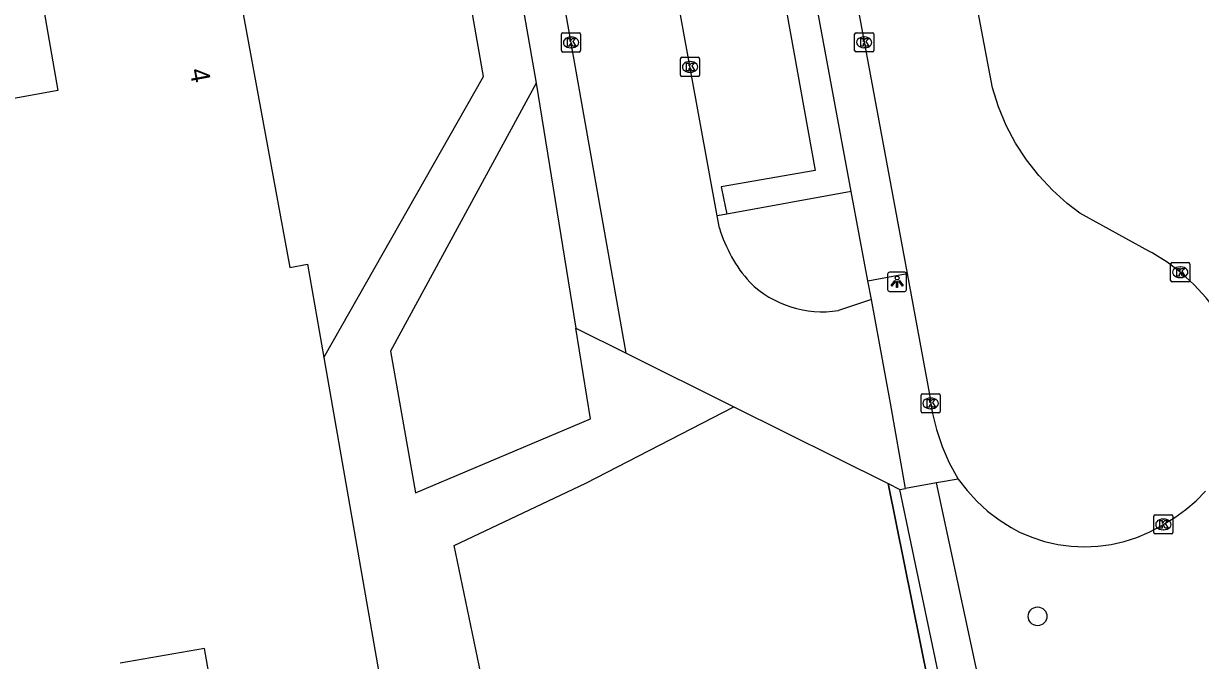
# Model space of a CAD drawing. Extents: x 159451 to 160663, y 388402 to 389723.
# Drawn here: x 159640.5 to 159701.9, y 388842.8 to 388876 of the extents above; entities that cross this region are included whole.
import ezdxf

# ---------------------------------------------------------------- set-up
doc = ezdxf.new("R2010")
doc.units = 0
for name, color, linetype in [('IMGEO_Boom', 7, 'Continuous'), ('IMGEO_Hek', 7, 'Continuous'), ('IMGEO_Kolk', 7, 'Continuous'), ('IMGEO_Lichtpunt', 7, 'Continuous'), ('IMGEO_Loofbos', 7, 'Continuous'), ('IMGEO_Muur', 7, 'Continuous'), ('IMGEO_Pand', 7, 'Continuous'), ('IMGEO_Pand_nummerreeks', 7, 'Continuous'), ('IMGEO_Parkeervlak_open', 7, 'Continuous'), ('IMGEO_Rijbaan_lokaal_open', 7, 'Continuous'), ('IMGEO_Voetpad_halfverhard', 7, 'Continuous'), ('IMGEO_Voetpad_open', 7, 'Continuous')]:
    doc.layers.add(name, color=color, linetype=linetype)

msp = doc.modelspace()

# ---------------------------------------------------------------- linework, layer by layer
at = {"layer": 'IMGEO_Boom'}
msp.add_circle((159693.409, 388845.115), 0.489, dxfattribs=at)
at = {"layer": 'IMGEO_Hek'}
msp.add_lwpolyline([(159685.613, 388852.043), (159688.561, 388837.482)], dxfattribs=at)
at = {"layer": 'IMGEO_Kolk'}
for p, q in [((159668.651, 388875.545), (159669.503, 388875.545)), ((159683.942, 388875.55), (159684.794, 388875.55)), ((159668.576, 388874.619), (159668.576, 388875.471)), ((159669.064, 388875.325), (159669.089, 388875.325)), ((159669.577, 388875.471), (159669.577, 388874.619)), ((159683.867, 388874.624), (159683.867, 388875.476)), ((159684.355, 388875.33), (159684.38, 388875.33)), ((159684.868, 388875.476), (159684.868, 388874.624)), ((159669.503, 388874.545), (159668.651, 388874.545)), ((159669.087, 388874.765), (159669.062, 388874.765)), ((159674.857, 388874.271), (159675.709, 388874.271)), ((159684.794, 388874.55), (159683.942, 388874.55)), ((159684.378, 388874.77), (159684.353, 388874.77)), ((159674.782, 388873.345), (159674.782, 388874.197)), ((159675.27, 388874.051), (159675.295, 388874.051)), ((159675.783, 388874.197), (159675.783, 388873.345)), ((159675.709, 388873.271), (159674.857, 388873.271)), ((159675.293, 388873.491), (159675.268, 388873.491)), ((159700.349, 388862.636), (159700.349, 388863.488)), ((159700.424, 388863.562), (159701.276, 388863.562)), ((159700.837, 388863.342), (159700.862, 388863.342)), ((159701.35, 388863.488), (159701.35, 388862.636)), ((159700.86, 388862.782), (159700.835, 388862.782)), ((159701.276, 388862.562), (159700.424, 388862.562)), ((159687.332, 388855.796), (159687.332, 388856.648)), ((159687.407, 388856.722), (159688.259, 388856.722)), ((159687.82, 388856.502), (159687.845, 388856.502)), ((159688.333, 388856.648), (159688.333, 388855.796)), ((159687.843, 388855.942), (159687.818, 388855.942)), ((159688.259, 388855.722), (159687.407, 388855.722)), ((159699.469, 388849.484), (159699.469, 388850.336)), ((159699.544, 388850.41), (159700.396, 388850.41)), ((159700.47, 388850.336), (159700.47, 388849.484)), ((159699.957, 388850.19), (159699.982, 388850.19)), ((159700.396, 388849.41), (159699.544, 388849.41)), ((159699.98, 388849.63), (159699.955, 388849.63))]:
    msp.add_line(p, q, dxfattribs=at)
for points in [[(159668.651, 388875.545), (159669.503, 388875.545)], [(159683.942, 388875.55), (159684.794, 388875.55)], [(159668.576, 388874.619), (159668.576, 388875.471)], [(159668.897, 388875.245), (159669.02, 388875.245), (159669.02, 388875.094), (159669.15, 388875.245), (159669.314, 388875.245), (159669.168, 388875.094), (159669.321, 388874.845), (159669.169, 388874.845), (159669.084, 388875.009), (159669.02, 388874.942), (159669.02, 388874.845), (159668.897, 388874.845), (159668.897, 388875.245)], [(159669.577, 388875.471), (159669.577, 388874.619)], [(159683.867, 388874.624), (159683.867, 388875.476)], [(159684.188, 388875.25), (159684.311, 388875.25), (159684.311, 388875.099), (159684.441, 388875.25), (159684.605, 388875.25), (159684.459, 388875.099), (159684.612, 388874.85), (159684.46, 388874.85), (159684.375, 388875.014), (159684.311, 388874.947), (159684.311, 388874.85), (159684.188, 388874.85), (159684.188, 388875.25)], [(159684.868, 388875.476), (159684.868, 388874.624)], [(159669.503, 388874.545), (159668.651, 388874.545)], [(159674.857, 388874.271), (159675.709, 388874.271)], [(159684.794, 388874.55), (159683.942, 388874.55)], [(159674.782, 388873.345), (159674.782, 388874.197)], [(159675.103, 388873.971), (159675.226, 388873.971), (159675.226, 388873.82), (159675.356, 388873.971), (159675.52, 388873.971), (159675.374, 388873.82), (159675.527, 388873.571), (159675.375, 388873.571), (159675.29, 388873.735), (159675.226, 388873.668), (159675.226, 388873.571), (159675.103, 388873.571), (159675.103, 388873.971)], [(159675.783, 388874.197), (159675.783, 388873.345)], [(159675.709, 388873.271), (159674.857, 388873.271)], [(159700.349, 388862.636), (159700.349, 388863.488)], [(159700.424, 388863.562), (159701.276, 388863.562)], [(159700.67, 388863.262), (159700.793, 388863.262), (159700.793, 388863.111), (159700.923, 388863.262), (159701.087, 388863.262), (159700.941, 388863.111), (159701.094, 388862.862), (159700.942, 388862.862), (159700.857, 388863.026), (159700.793, 388862.959), (159700.793, 388862.862), (159700.67, 388862.862), (159700.67, 388863.262)], [(159701.35, 388863.488), (159701.35, 388862.636)], [(159701.276, 388862.562), (159700.424, 388862.562)], [(159687.332, 388855.796), (159687.332, 388856.648)], [(159687.407, 388856.722), (159688.259, 388856.722)], [(159688.333, 388856.648), (159688.333, 388855.796)], [(159687.653, 388856.422), (159687.776, 388856.422), (159687.776, 388856.271), (159687.906, 388856.422), (159688.07, 388856.422), (159687.924, 388856.271), (159688.077, 388856.022), (159687.925, 388856.022), (159687.84, 388856.186), (159687.776, 388856.119), (159687.776, 388856.022), (159687.653, 388856.022), (159687.653, 388856.422)], [(159688.259, 388855.722), (159687.407, 388855.722)], [(159699.469, 388849.484), (159699.469, 388850.336)], [(159699.544, 388850.41), (159700.396, 388850.41)], [(159700.47, 388850.336), (159700.47, 388849.484)], [(159699.79, 388850.11), (159699.913, 388850.11), (159699.913, 388849.959), (159700.043, 388850.11), (159700.207, 388850.11), (159700.061, 388849.959), (159700.214, 388849.71), (159700.062, 388849.71), (159699.977, 388849.874), (159699.913, 388849.807), (159699.913, 388849.71), (159699.79, 388849.71), (159699.79, 388850.11)], [(159700.396, 388849.41), (159699.544, 388849.41)]]:
    msp.add_lwpolyline(points, dxfattribs=at)
for centre, start, end in [((159668.653, 388875.469), 91.55205, 178.44795), ((159668.653, 388875.469), 91.55205, 178.44795), ((159669.501, 388875.469), 1.55205, 88.44795), ((159669.501, 388875.469), 1.55205, 88.44795), ((159683.944, 388875.474), 91.55205, 178.44795), ((159683.944, 388875.474), 91.55205, 178.44795), ((159684.792, 388875.474), 1.55205, 88.44795), ((159684.792, 388875.474), 1.55205, 88.44795), ((159668.653, 388874.621), 181.55205, 268.44795), ((159668.653, 388874.621), 181.55205, 268.44795), ((159669.501, 388874.621), 271.55205, 358.44795), ((159669.501, 388874.621), 271.55205, 358.44795), ((159674.859, 388874.195), 91.55205, 178.44795), ((159674.859, 388874.195), 91.55205, 178.44795), ((159675.707, 388874.195), 1.55205, 88.44795), ((159675.707, 388874.195), 1.55205, 88.44795), ((159683.944, 388874.626), 181.55205, 268.44795), ((159683.944, 388874.626), 181.55205, 268.44795), ((159684.792, 388874.626), 271.55205, 358.44795), ((159684.792, 388874.626), 271.55205, 358.44795), ((159674.859, 388873.347), 181.55205, 268.44795), ((159674.859, 388873.347), 181.55205, 268.44795), ((159675.707, 388873.347), 271.55205, 358.44795), ((159675.707, 388873.347), 271.55205, 358.44795), ((159700.426, 388863.486), 91.55205, 178.44795), ((159700.426, 388863.486), 91.55205, 178.44795), ((159701.274, 388863.486), 1.55205, 88.44795), ((159701.274, 388863.486), 1.55205, 88.44795), ((159700.426, 388862.638), 181.55205, 268.44795), ((159700.426, 388862.638), 181.55205, 268.44795), ((159701.274, 388862.638), 271.55205, 358.44795), ((159701.274, 388862.638), 271.55205, 358.44795), ((159687.409, 388856.646), 91.55205, 178.44795), ((159687.409, 388856.646), 91.55205, 178.44795), ((159688.257, 388856.646), 1.55205, 88.44795), ((159688.257, 388856.646), 1.55205, 88.44795), ((159687.409, 388855.798), 181.55205, 268.44795), ((159687.409, 388855.798), 181.55205, 268.44795), ((159688.257, 388855.798), 271.55205, 358.44795), ((159688.257, 388855.798), 271.55205, 358.44795), ((159699.546, 388850.334), 91.55205, 178.44795), ((159699.546, 388850.334), 91.55205, 178.44795), ((159700.394, 388850.334), 1.55205, 88.44795), ((159700.394, 388850.334), 1.55205, 88.44795), ((159699.546, 388849.486), 181.55205, 268.44795), ((159699.546, 388849.486), 181.55205, 268.44795), ((159700.394, 388849.486), 271.55205, 358.44795), ((159700.394, 388849.486), 271.55205, 358.44795)]:
    msp.add_arc(centre, 0.0765, start, end, dxfattribs=at)
for centre, major_axis, ratio, start_param, end_param in [((159669.063, 388875.045), (-0.387, 0.002), 0.722429, 4.712389, 7.853982), ((159669.088, 388875.045), (-0.39, 0.002), 0.717154, 1.570796, 4.712389), ((159684.354, 388875.05), (-0.387, 0.002), 0.722429, 4.712389, 7.853982), ((159684.379, 388875.05), (-0.39, 0.002), 0.717154, 1.570796, 4.712389), ((159675.269, 388873.771), (-0.387, 0.002), 0.722429, 4.712389, 7.853982), ((159675.294, 388873.771), (-0.39, 0.002), 0.717154, 1.570796, 4.712389), ((159700.836, 388863.062), (-0.387, 0.002), 0.722429, 4.712389, 7.853982), ((159700.861, 388863.062), (-0.39, 0.002), 0.717154, 1.570796, 4.712389), ((159687.819, 388856.222), (-0.387, 0.002), 0.722429, 4.712389, 7.853982), ((159687.844, 388856.222), (-0.39, 0.002), 0.717154, 1.570796, 4.712389), ((159699.956, 388849.91), (-0.387, 0.002), 0.722429, 4.712389, 7.853982), ((159699.981, 388849.91), (-0.39, 0.002), 0.717154, 1.570796, 4.712389)]:
    msp.add_ellipse(centre, major_axis=major_axis, ratio=ratio, start_param=start_param, end_param=end_param, dxfattribs=at)
at = {"layer": 'IMGEO_Lichtpunt'}
for p, q in [((159685.584, 388862.962), (159685.584, 388862.155)), ((159685.584, 388862.962), (159685.584, 388862.155)), ((159686.486, 388863.057), (159685.678, 388863.057)), ((159686.486, 388863.057), (159685.678, 388863.057)), ((159686.58, 388862.155), (159686.58, 388862.962)), ((159686.58, 388862.155), (159686.58, 388862.962)), ((159685.678, 388862.061), (159686.486, 388862.061)), ((159685.678, 388862.061), (159686.486, 388862.061))]:
    msp.add_line(p, q, dxfattribs=at)
for points in [[(159685.958, 388862.626), (159685.997, 388862.598), (159685.809, 388862.336), (159685.771, 388862.363), (159685.958, 388862.626)], [(159686.17, 388862.598), (159686.208, 388862.625), (159686.395, 388862.363), (159686.356, 388862.335), (159686.17, 388862.598)], [(159686.06, 388862.578), (159686.107, 388862.578), (159686.107, 388862.256), (159686.06, 388862.256), (159686.06, 388862.578)]]:
    msp.add_lwpolyline(points, dxfattribs=at)
msp.add_circle((159686.083, 388862.76), 0.0994, dxfattribs=at)
for centre, start, end in [((159685.678, 388862.962), 90, 180), ((159685.678, 388862.962), 90, 180), ((159686.486, 388862.962), 0, 90), ((159686.486, 388862.962), 0, 90), ((159685.678, 388862.155), 180, 270), ((159685.678, 388862.155), 180, 270), ((159686.486, 388862.155), 270, 0), ((159686.486, 388862.155), 270, 360)]:
    msp.add_arc(centre, 0.0946, start, end, dxfattribs=at)
at = {"layer": 'IMGEO_Loofbos'}
msp.add_lwpolyline([(159538.553, 388875.669), (159562.528, 388756.756), (159678.25, 388782.74), (159689.421, 388833.236), (159688.561, 388837.482), (159685.613, 388852.043)], dxfattribs=at)
at = {"layer": 'IMGEO_Muur'}
for points in [[(159683.694, 388867.275), (159681.068, 388881.449), (159678.498, 388895.409)], [(159672.023, 388894.206), (159672.355, 388892.368), (159677.318, 388893.266), (159681.802, 388868.361), (159676.915, 388867.519), (159677.034, 388866.93), (159677.206, 388866.087)], [(159683.694, 388867.275), (159677.206, 388866.087)]]:
    msp.add_lwpolyline(points, dxfattribs=at)
at = {"layer": 'IMGEO_Pand'}
for points in [[(159649.385, 388920.318), (159651.233, 388910.205), (159650.908, 388910.146), (159653.635, 388895.213), (159653.68, 388894.967), (159656.268, 388895.439), (159657.177, 388890.462), (159654.589, 388889.989), (159654.634, 388889.743), (159655.416, 388885.464), (159650.497, 388884.566), (159654.41, 388863.313), (159655.341, 388863.475), (159656.187, 388858.62)], [(159630.838, 388863.145), (159627.72, 388880.372), (159640.538, 388882.732), (159642.317, 388872.531), (159635.149, 388871.234), (159636.43, 388864.158), (159630.838, 388863.145)], [(159656.187, 388858.62), (159659.172, 388841.486)], [(159650.562, 388839.986), (159649.961, 388843.435), (159645.57, 388842.67)]]:
    msp.add_lwpolyline(points, dxfattribs=at)
at = {"layer": 'IMGEO_Parkeervlak_open'}
for points in [[(159667.257, 388872.925), (159669.328, 388860.143)], [(159677.206, 388866.087), (159676.699, 388866.003)]]:
    msp.add_lwpolyline(points, dxfattribs=at)
at = {"layer": 'IMGEO_Rijbaan_lokaal_open'}
for points in [[(159676.123, 388919.495), (159686.606, 388862.993)], [(159703.685, 388859.407), (159703.262, 388860.224), (159702.768, 388861.001), (159702.206, 388861.73), (159701.582, 388862.406), (159700.899, 388863.023), (159700.164, 388863.578), (159699.383, 388864.064), (159699.217, 388864.155), (159695.614, 388866.147), (159694.957, 388866.645), (159694.18, 388867.339), (159693.468, 388868.1), (159692.827, 388868.921), (159692.261, 388869.796), (159691.776, 388870.719), (159691.376, 388871.68), (159691.063, 388872.674), (159686.514, 388896.65), (159683.633, 388912.346)], [(159676.699, 388866.003), (159671.575, 388894.125)], [(159671.949, 388858.84), (159670.127, 388869.124), (159666.75, 388888.181), (159666.095, 388891.836), (159666.069, 388891.98)], [(159676.818, 388865.36), (159676.699, 388866.003)], [(159686.606, 388862.993), (159687.778, 388856.678), (159687.913, 388855.759), (159688.13, 388854.856), (159688.426, 388853.975), (159688.8, 388853.125), (159689.249, 388852.311), (159689.271, 388852.275)], [(159684.739, 388861.634), (159683.026, 388861.066)], [(159686.526, 388851.79), (159685.74, 388856.234), (159684.739, 388861.634)], [(159671.949, 388858.84), (159677.571, 388856.044)], [(159677.571, 388856.044), (159685.613, 388852.043)], [(159689.271, 388852.275), (159689.729, 388851.673), (159690.239, 388851.114), (159690.797, 388850.603), (159691.398, 388850.144), (159692.038, 388849.741), (159692.47, 388849.511), (159693.113, 388849.237), (159693.778, 388849.021), (159694.46, 388848.865), (159695.153, 388848.771), (159695.851, 388848.739), (159696.55, 388848.77), (159697.243, 388848.863), (159697.925, 388849.017), (159698.59, 388849.232), (159699.234, 388849.506), (159699.851, 388849.836), (159699.967, 388849.906), (159700.572, 388850.267), (159701.142, 388850.68), (159701.673, 388851.142), (159702.16, 388851.65)], [(159685.613, 388852.043), (159686.229, 388851.737)], [(159686.229, 388851.737), (159686.526, 388851.79)]]:
    msp.add_lwpolyline(points, dxfattribs=at)
for centre, radius, start, end in [((159683.924, 388867.487), 7.417, 196.66138, 221.83009), ((159682.183, 388866.425), 5.425, 225.73861, 278.9356)]:
    msp.add_arc(centre, radius, start, end, dxfattribs=at)
at = {"layer": 'IMGEO_Voetpad_halfverhard'}
for points in [[(159666.766, 388725.317), (159672.123, 388750), (159679.188, 388782.55), (159690.146, 388833.037), (159689.111, 388837.976), (159686.229, 388851.737)], [(159691.922, 388831.802), (159692.206, 388833.101), (159690.83, 388839.519), (159688.139, 388852.075)]]:
    msp.add_lwpolyline(points, dxfattribs=at)
at = {"layer": 'IMGEO_Voetpad_open'}
for points in [[(159656.187, 388858.62), (159664.511, 388873.264), (159661.405, 388890.98), (159660.445, 388896.457), (159656.968, 388916.294), (159649.385, 388920.318)], [(159666.069, 388891.98), (159663.993, 388891.631), (159667.257, 388872.925)], [(159667.257, 388872.925), (159659.66, 388858.946), (159660.961, 388851.556), (159670.093, 388855.423), (159669.328, 388860.143)], [(159684.558, 388862.613), (159683.694, 388867.275)], [(159684.558, 388862.613), (159686.606, 388862.993)], [(159684.739, 388861.634), (159684.558, 388862.613)], [(159669.328, 388860.143), (159671.949, 388858.84)], [(159663.917, 388832.098), (159665.856, 388835.05), (159662.982, 388848.818), (159669.854, 388852.057), (159677.571, 388856.044)], [(159689.271, 388852.275), (159688.139, 388852.075)], [(159688.139, 388852.075), (159686.526, 388851.79)]]:
    msp.add_lwpolyline(points, dxfattribs=at)

# ---------------------------------------------------------------- texts
at = {"layer": 'IMGEO_Pand_nummerreeks'}
msp.add_text('4', height=1, rotation=280.43219, dxfattribs=at).set_placement((159649.179, 388873.613))

doc.saveas('drawing.dxf')
